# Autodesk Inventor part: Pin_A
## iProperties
Shininess: 0.0
Length Units: 11272
Angle Units: 11279
Time Units: 11290
Mass Units: 11283
Length Display Precision: 2
Angle Display Precision: 1
Created: 1999-05
Part Number: Pin_A
Document SubType Name: Modeling
Designer: Administrator
Density: 1 g/cm^3
Density: 0.0
Volumn: 0.0
Area: 0.0
PropertySet Name: Model Information
Control State: 0
Master: False
Checked Out: False
Author: Administrator
